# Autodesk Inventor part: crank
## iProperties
Created: 2002-08
Part Number: crank
Document SubType Name: Modeling
Designer: t_munrn
Density: 1 g/cm^3
Control State: 0
Master: False
Checked Out: False
Shininess: 64.0
Length Units: 11269
Angle Units: 11279
Time Units: 11290
Mass Units: 11283
Length Display Precision: 3
Angle Display Precision: 2
Density: 0.0
Volumn: 0.0
Area: 0.0
PropertySet Name: Model Information
Author: t_munrn
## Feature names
1. Extrusion1
2. Extrusion11
3. Extrusion2
4. Fillet1
5. Revolution1
6. Fillet5
7. Extrusion7
8. Fillet8
9. Fillet9
10. Mirror2
11. Extrusion8
12. Hole1
13. Circular Pattern1
14. Extrusion9
15. Chamfer3
16. Extrusion10
17. Chamfer4
18. Fillet7
19. Fillet10
